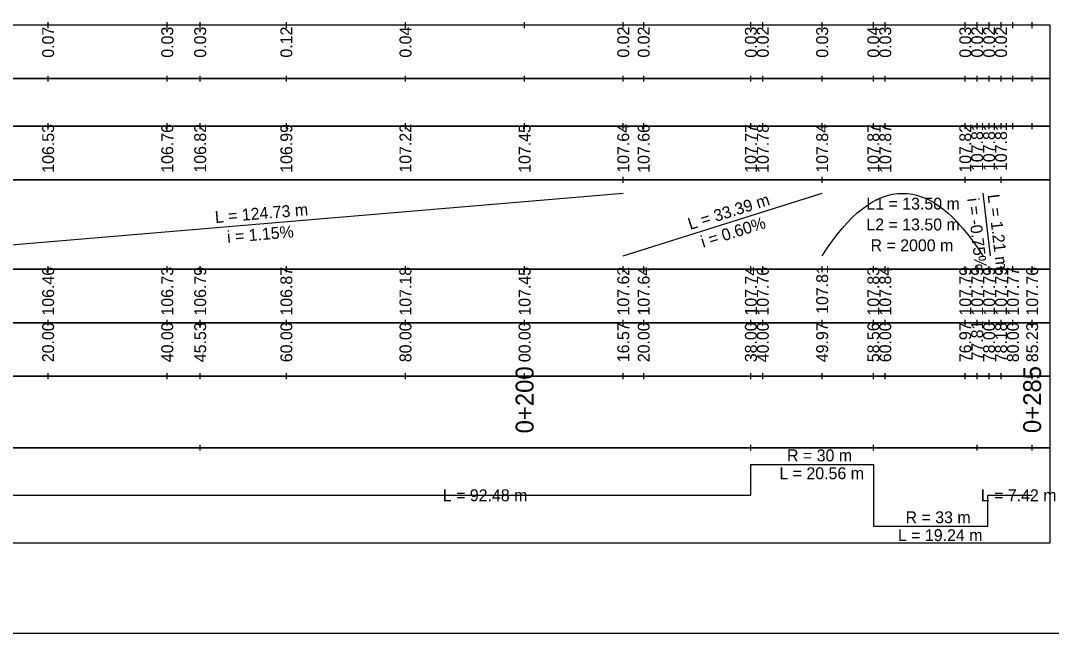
# Model space of a CAD drawing. Extents: x 7481207 to 7481727, y 5776531 to 5776815.
# Drawn here: x 7481380.5 to 7481553.6, y 5776530.9 to 5776633.9 of the extents above; entities that cross this region are included whole.
import ezdxf

# ---------------------------------------------------------------- set-up
doc = ezdxf.new("R2010")
doc.units = 0
for name, color, linetype in [('d_p_tabela', 7, 'Continuous'), ('prof_tabela_txt', 7, 'Continuous'), ('ramka', 7, 'Continuous'), ('tabela_p', 7, 'Continuous'), ('tabela_txt_p', 7, 'Continuous')]:
    doc.layers.add(name, color=color, linetype=linetype)

msp = doc.modelspace()

# ---------------------------------------------------------------- linework, layer by layer
at = {"layer": 'd_p_tabela'}
for points in [[(7481262.15, 5776624.1), (7481553.38, 5776624.1), (7481553.38, 5776633.1), (7481262.15, 5776633.1)], [(7481262.15, 5776616.1), (7481553.38, 5776616.1), (7481553.38, 5776624.1), (7481262.15, 5776624.1)], [(7481262.15, 5776607.1), (7481553.38, 5776607.1), (7481553.38, 5776616.1), (7481262.15, 5776616.1)], [(7481262.15, 5776592.1), (7481553.38, 5776592.1), (7481553.38, 5776607.1), (7481262.15, 5776607.1)], [(7481262.15, 5776583.1), (7481553.38, 5776583.1), (7481553.38, 5776592.1), (7481262.15, 5776592.1)], [(7481262.15, 5776574.1), (7481553.38, 5776574.1), (7481553.38, 5776583.1), (7481262.15, 5776583.1)], [(7481262.15, 5776562.1), (7481553.38, 5776562.1), (7481553.38, 5776574.1), (7481262.15, 5776574.1)], [(7481262.15, 5776546.1), (7481553.38, 5776546.1), (7481553.38, 5776562.1), (7481262.15, 5776562.1)]]:
    msp.add_lwpolyline(points, close=True, dxfattribs=at)
for points in [[(7481385.15, 5776632.6), (7481385.15, 5776633.6)], [(7481405.15, 5776632.6), (7481405.15, 5776633.6)], [(7481410.68, 5776632.6), (7481410.68, 5776633.6)], [(7481425.15, 5776632.6), (7481425.15, 5776633.6)], [(7481445.15, 5776632.6), (7481445.15, 5776633.6)], [(7481465.15, 5776632.6), (7481465.15, 5776633.6)], [(7481481.72, 5776632.6), (7481481.72, 5776633.6)], [(7481485.15, 5776632.6), (7481485.15, 5776633.6)], [(7481503.15, 5776632.6), (7481503.15, 5776633.6)], [(7481505.15, 5776632.6), (7481505.15, 5776633.6)], [(7481515.12, 5776632.6), (7481515.12, 5776633.6)], [(7481523.71, 5776632.6), (7481523.71, 5776633.6)], [(7481525.71, 5776632.6), (7481525.71, 5776633.6)], [(7481539.15, 5776632.6), (7481539.15, 5776633.6)], [(7481541.15, 5776632.6), (7481541.15, 5776633.6)], [(7481543.15, 5776632.6), (7481543.15, 5776633.6)], [(7481545.15, 5776632.6), (7481545.15, 5776633.6)], [(7481547.15, 5776632.6), (7481547.15, 5776633.6)], [(7481550.38, 5776632.6), (7481550.38, 5776633.6)], [(7481385.15, 5776623.6), (7481385.15, 5776624.6)], [(7481405.15, 5776623.6), (7481405.15, 5776624.6)], [(7481410.68, 5776623.6), (7481410.68, 5776624.6)], [(7481425.15, 5776623.6), (7481425.15, 5776624.6)], [(7481445.15, 5776623.6), (7481445.15, 5776624.6)], [(7481465.15, 5776623.6), (7481465.15, 5776624.6)], [(7481481.72, 5776623.6), (7481481.72, 5776624.6)], [(7481485.15, 5776623.6), (7481485.15, 5776624.6)], [(7481503.15, 5776623.6), (7481503.15, 5776624.6)], [(7481505.15, 5776623.6), (7481505.15, 5776624.6)], [(7481515.12, 5776623.6), (7481515.12, 5776624.6)], [(7481523.71, 5776623.6), (7481523.71, 5776624.6)], [(7481525.71, 5776623.6), (7481525.71, 5776624.6)], [(7481539.15, 5776623.6), (7481539.15, 5776624.6)], [(7481541.15, 5776623.6), (7481541.15, 5776624.6)], [(7481543.15, 5776623.6), (7481543.15, 5776624.6)], [(7481545.15, 5776623.6), (7481545.15, 5776624.6)], [(7481547.15, 5776623.6), (7481547.15, 5776624.6)], [(7481550.38, 5776623.6), (7481550.38, 5776624.6)], [(7481385.15, 5776615.6), (7481385.15, 5776616.6)], [(7481405.15, 5776615.6), (7481405.15, 5776616.6)], [(7481410.68, 5776615.6), (7481410.68, 5776616.6)], [(7481425.15, 5776615.6), (7481425.15, 5776616.6)], [(7481445.15, 5776615.6), (7481445.15, 5776616.6)], [(7481465.15, 5776615.6), (7481465.15, 5776616.6)], [(7481481.72, 5776615.6), (7481481.72, 5776616.6)], [(7481485.15, 5776615.6), (7481485.15, 5776616.6)], [(7481503.15, 5776615.6), (7481503.15, 5776616.6)], [(7481505.15, 5776615.6), (7481505.15, 5776616.6)], [(7481515.12, 5776615.6), (7481515.12, 5776616.6)], [(7481523.71, 5776615.6), (7481523.71, 5776616.6)], [(7481525.71, 5776615.6), (7481525.71, 5776616.6)], [(7481539.15, 5776615.6), (7481539.15, 5776616.6)], [(7481541.15, 5776615.6), (7481541.15, 5776616.6)], [(7481543.15, 5776615.6), (7481543.15, 5776616.6)], [(7481545.15, 5776615.6), (7481545.15, 5776616.6)], [(7481547.15, 5776615.6), (7481547.15, 5776616.6)], [(7481550.38, 5776615.6), (7481550.38, 5776616.6)], [(7481481.72, 5776606.6), (7481481.72, 5776607.6)], [(7481515.12, 5776606.6), (7481515.12, 5776607.6)], [(7481539.15, 5776606.6), (7481539.15, 5776607.6)], [(7481545.15, 5776606.6), (7481545.15, 5776607.6)], [(7481385.15, 5776591.6), (7481385.15, 5776592.6)], [(7481405.15, 5776591.6), (7481405.15, 5776592.6)], [(7481410.68, 5776591.6), (7481410.68, 5776592.6)], [(7481425.15, 5776591.6), (7481425.15, 5776592.6)], [(7481445.15, 5776591.6), (7481445.15, 5776592.6)], [(7481465.15, 5776591.6), (7481465.15, 5776592.6)], [(7481481.72, 5776591.6), (7481481.72, 5776592.6)], [(7481485.15, 5776591.6), (7481485.15, 5776592.6)], [(7481503.15, 5776591.6), (7481503.15, 5776592.6)], [(7481505.15, 5776591.6), (7481505.15, 5776592.6)], [(7481515.12, 5776591.6), (7481515.12, 5776592.6)], [(7481523.71, 5776591.6), (7481523.71, 5776592.6)], [(7481525.71, 5776591.6), (7481525.71, 5776592.6)], [(7481539.15, 5776591.6), (7481539.15, 5776592.6)], [(7481541.15, 5776591.6), (7481541.15, 5776592.6)], [(7481543.15, 5776591.6), (7481543.15, 5776592.6)], [(7481545.15, 5776591.6), (7481545.15, 5776592.6)], [(7481547.15, 5776591.6), (7481547.15, 5776592.6)], [(7481550.38, 5776591.6), (7481550.38, 5776592.6)], [(7481385.15, 5776582.6), (7481385.15, 5776583.6)], [(7481405.15, 5776582.6), (7481405.15, 5776583.6)], [(7481410.68, 5776582.6), (7481410.68, 5776583.6)], [(7481425.15, 5776582.6), (7481425.15, 5776583.6)], [(7481445.15, 5776582.6), (7481445.15, 5776583.6)], [(7481465.15, 5776582.6), (7481465.15, 5776583.6)], [(7481481.72, 5776582.6), (7481481.72, 5776583.6)], [(7481485.15, 5776582.6), (7481485.15, 5776583.6)], [(7481503.15, 5776582.6), (7481503.15, 5776583.6)], [(7481505.15, 5776582.6), (7481505.15, 5776583.6)], [(7481515.12, 5776582.6), (7481515.12, 5776583.6)], [(7481523.71, 5776582.6), (7481523.71, 5776583.6)], [(7481525.71, 5776582.6), (7481525.71, 5776583.6)], [(7481539.15, 5776582.6), (7481539.15, 5776583.6)], [(7481541.15, 5776582.6), (7481541.15, 5776583.6)], [(7481543.15, 5776582.6), (7481543.15, 5776583.6)], [(7481545.15, 5776582.6), (7481545.15, 5776583.6)], [(7481547.15, 5776582.6), (7481547.15, 5776583.6)], [(7481550.38, 5776582.6), (7481550.38, 5776583.6)], [(7481385.15, 5776573.6), (7481385.15, 5776574.6)], [(7481405.15, 5776573.6), (7481405.15, 5776574.6)], [(7481410.68, 5776573.6), (7481410.68, 5776574.6)], [(7481425.15, 5776573.6), (7481425.15, 5776574.6)], [(7481445.15, 5776573.6), (7481445.15, 5776574.6)], [(7481465.15, 5776573.6), (7481465.15, 5776574.6)], [(7481481.72, 5776573.6), (7481481.72, 5776574.6)], [(7481485.15, 5776573.6), (7481485.15, 5776574.6)], [(7481503.15, 5776573.6), (7481503.15, 5776574.6)], [(7481505.15, 5776573.6), (7481505.15, 5776574.6)], [(7481515.12, 5776573.6), (7481515.12, 5776574.6)], [(7481523.71, 5776573.6), (7481523.71, 5776574.6)], [(7481525.71, 5776573.6), (7481525.71, 5776574.6)], [(7481539.15, 5776573.6), (7481539.15, 5776574.6)], [(7481541.15, 5776573.6), (7481541.15, 5776574.6)], [(7481543.15, 5776573.6), (7481543.15, 5776574.6)], [(7481545.15, 5776573.6), (7481545.15, 5776574.6)], [(7481550.38, 5776573.6), (7481550.38, 5776574.6)], [(7481410.68, 5776561.6), (7481410.68, 5776562.6)], [(7481503.15, 5776561.6), (7481503.15, 5776562.6)], [(7481523.71, 5776561.6), (7481523.71, 5776562.6)], [(7481541.15, 5776561.6), (7481541.15, 5776562.6)], [(7481550.38, 5776561.6), (7481550.38, 5776562.6)]]:
    msp.add_lwpolyline(points, dxfattribs=at)
at = {"layer": 'ramka'}
for points in [[(7481207.45, 5776814.89), (7481727.02, 5776814.89), (7481727.02, 5776530.89), (7481207.45, 5776530.89)], [(7481207.45, 5776814.89), (7481567.02, 5776814.89), (7481567.02, 5776530.89), (7481207.45, 5776530.89)]]:
    msp.add_lwpolyline(points, close=True, dxfattribs=at)
at = {"layer": 'tabela_p'}
for points in [[(7481357, 5776594.35), (7481481.72, 5776604.85)], [(7481481.72, 5776594.35), (7481515.12, 5776604.85)], [(7481515.12, 5776594.35), (7481515.96, 5776595.63), (7481516.8, 5776596.82), (7481517.65, 5776597.92), (7481518.49, 5776598.95), (7481519.34, 5776599.89), (7481520.18, 5776600.75), (7481521.02, 5776601.53), (7481521.87, 5776602.23), (7481522.71, 5776602.84), (7481523.55, 5776603.38), (7481524.4, 5776603.83), (7481525.24, 5776604.2), (7481526.09, 5776604.49), (7481526.93, 5776604.69), (7481527.77, 5776604.81), (7481529.46, 5776604.81), (7481530.3, 5776604.69), (7481531.15, 5776604.49), (7481531.99, 5776604.2), (7481532.84, 5776603.83), (7481533.68, 5776603.38), (7481534.52, 5776602.84), (7481535.37, 5776602.23), (7481536.21, 5776601.53), (7481537.05, 5776600.75), (7481537.9, 5776599.89), (7481538.74, 5776598.95), (7481539.59, 5776597.92), (7481540.43, 5776596.82), (7481541.27, 5776595.63), (7481542.12, 5776594.35)], [(7481542.12, 5776604.85), (7481543.33, 5776594.35)], [(7481265.15, 5776554.1), (7481274.77, 5776554.1), (7481274.77, 5776548.9), (7481308.62, 5776548.9), (7481308.62, 5776554.1), (7481410.68, 5776554.1), (7481410.68, 5776554.1), (7481503.15, 5776554.1), (7481503.15, 5776559.3), (7481523.71, 5776559.3), (7481523.71, 5776548.9), (7481542.96, 5776548.9), (7481542.96, 5776554.1), (7481550.38, 5776554.1)]]:
    msp.add_lwpolyline(points, dxfattribs=at)

# ---------------------------------------------------------------- texts
at = {"layer": 'prof_tabela_txt'}
for s, p in [('0+200', (7481466.65, 5776564.5)), ('0+285', (7481551.88, 5776564.55))]:
    msp.add_text(s, height=3, rotation=90, dxfattribs=at).set_placement(p)
at = {"layer": 'tabela_txt_p'}
for s, rotation, p in [('0.07', 90, (7481386.15, 5776627.62)), ('0.03', 90, (7481406.15, 5776627.62)), ('0.03', 90, (7481411.68, 5776627.62)), ('0.12', 90, (7481426.15, 5776627.64)), ('0.04', 90, (7481446.15, 5776627.63)), ('0.02', 90, (7481482.72, 5776627.64)), ('0.02', 90, (7481486.15, 5776627.64)), ('0.03', 90, (7481504.15, 5776627.62)), ('0.02', 90, (7481506.15, 5776627.64)), ('0.03', 90, (7481516.12, 5776627.62)), ('0.04', 90, (7481524.71, 5776627.63)), ('0.03', 90, (7481526.71, 5776627.62)), ('0.03', 90, (7481540.15, 5776627.62)), ('0.02', 90, (7481542.15, 5776627.64)), ('0.02', 90, (7481544.15, 5776627.64)), ('0.02', 90, (7481546.15, 5776627.64)), ('106.53', 90, (7481386.15, 5776608.29)), ('106.76', 90, (7481406.15, 5776608.29)), ('106.82', 90, (7481411.68, 5776608.31)), ('106.99', 90, (7481426.15, 5776608.29)), ('107.22', 90, (7481446.15, 5776608.31)), ('107.45', 90, (7481466.15, 5776608.28)), ('107.64', 90, (7481482.72, 5776608.3)), ('107.66', 90, (7481486.15, 5776608.29)), ('107.77', 90, (7481504.15, 5776608.29)), ('107.78', 90, (7481506.15, 5776608.29)), ('107.84', 90, (7481516.12, 5776608.3)), ('107.87', 90, (7481524.71, 5776608.29)), ('107.87', 90, (7481526.71, 5776608.29)), ('107.82', 90, (7481540.15, 5776608.31)), ('107.81', 90, (7481542.15, 5776608.58)), ('107.81', 90, (7481544.15, 5776608.58)), ('107.81', 90, (7481546.15, 5776608.58)), ('L = 33.39 m', 17.4542, (7481492.95, 5776598.67)), ('i = -0.75%', 276.5888, (7481539.45, 5776603.94)), ('L = 1.21 m', 276.5888, (7481542.9, 5776604.57)), ('L = 124.73 m', 4.8121, (7481413.24, 5776599.84)), ('i = 0.60%', 17.4542, (7481495.11, 5776595.68)), ('i = 1.15%', 4.8121, (7481415.27, 5776596.5)), ('106.46', 90, (7481386.15, 5776584.29)), ('106.73', 90, (7481406.15, 5776584.29)), ('106.79', 90, (7481411.68, 5776584.29)), ('106.87', 90, (7481426.15, 5776584.29)), ('107.18', 90, (7481446.15, 5776584.29)), ('107.45', 90, (7481466.15, 5776584.28)), ('107.62', 90, (7481482.72, 5776584.31)), ('107.64', 90, (7481486.15, 5776584.3)), ('107.74', 90, (7481504.15, 5776584.3)), ('107.76', 90, (7481506.15, 5776584.29)), ('107.81', 90, (7481516.12, 5776584.58)), ('107.83', 90, (7481524.71, 5776584.29)), ('107.84', 90, (7481526.71, 5776584.3)), ('107.79', 90, (7481540.15, 5776584.29)), ('107.79', 90, (7481542.15, 5776584.29)), ('107.79', 90, (7481544.15, 5776584.29)), ('107.79', 90, (7481546.15, 5776584.29)), ('107.77', 90, (7481548.15, 5776584.29)), ('107.76', 90, (7481551.38, 5776584.29)), ('20.00', 90, (7481386.15, 5776576.46)), ('40.00', 90, (7481406.15, 5776576.46)), ('45.53', 90, (7481411.68, 5776576.46)), ('60.00', 90, (7481426.15, 5776576.46)), ('80.00', 90, (7481446.15, 5776576.46)), ('00.00', 90, (7481466.15, 5776576.46)), ('16.57', 90, (7481482.72, 5776576.46)), ('20.00', 90, (7481486.15, 5776576.46)), ('38.00', 90, (7481504.15, 5776576.46)), ('40.00', 90, (7481506.15, 5776576.46)), ('49.97', 90, (7481516.12, 5776576.46)), ('58.56', 90, (7481524.71, 5776576.46)), ('60.00', 90, (7481526.71, 5776576.46)), ('76.97', 90, (7481540.15, 5776576.46)), ('77.81', 90, (7481542.15, 5776576.75)), ('78.00', 90, (7481544.15, 5776576.46)), ('78.18', 90, (7481546.15, 5776576.45)), ('80.00', 90, (7481548.15, 5776576.46)), ('85.23', 90, (7481551.38, 5776576.46))]:
    msp.add_text(s, height=2, rotation=rotation, dxfattribs=at).set_placement(p)
for s, p in [('L1 = 13.50 m', (7481522.54, 5776602.1)), ('L2 = 13.50 m', (7481522.54, 5776598.6)), ('R = 2000 m', (7481523.24, 5776595.1)), ('R = 30 m', (7481509.22, 5776559.8)), ('L = 20.56 m', (7481507.94, 5776556.8)), ('L = 92.48 m', (7481451.42, 5776553.1)), ('L = 7.42 m', (7481541.76, 5776553.1)), ('R = 33 m', (7481529.12, 5776549.4)), ('L = 19.24 m', (7481527.84, 5776546.4))]:
    msp.add_text(s, height=2, dxfattribs=at).set_placement(p)

doc.saveas('drawing.dxf')
